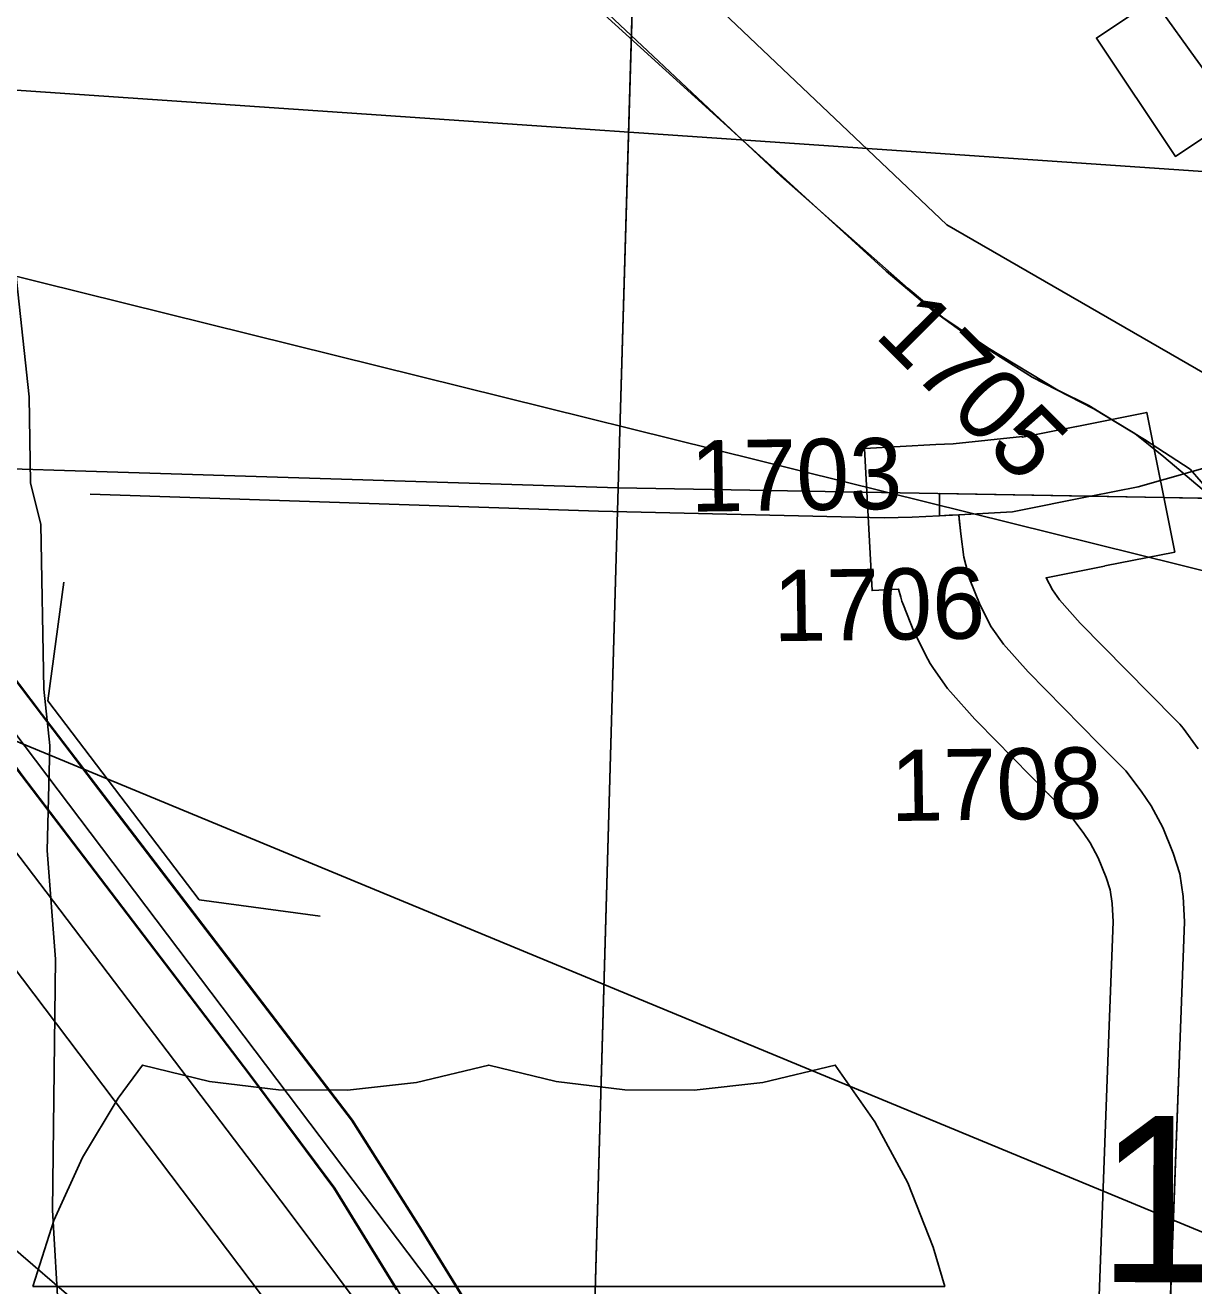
# Model space of a CAD drawing. Extents: x -132.8 to -73.3, y -60 to -26.
# Drawn here: x -121.236 to -120.744, y -52.636 to -52.105 of the extents above; entities that cross this region are included whole.
import ezdxf

# ---------------------------------------------------------------- set-up
doc = ezdxf.new("R2010")
doc.units = 0
for name, color, linetype in [('tdCoCityStreetMajor', 7, 'Continuous'), ('tdCoCityStreetMinor', 7, 'Continuous'), ('tdCoCorpBndry', 7, 'Continuous'), ('tdCoDivCarto', 7, 'Continuous'), ('tdCoHydroRiver', 7, 'Continuous'), ('tdCoInt', 7, 'Continuous'), ('tdCoIntCL', 7, 'Continuous'), ('tdCoIntRte', 7, 'Continuous'), ('tdCoPipe', 7, 'Continuous'), ('tdCoPrimary', 7, 'Continuous'), ('tdCoRRCL', 7, 'Continuous'), ('tdCoSecRdNmbr', 7, 'Continuous'), ('tdCoSecRteBand', 7, 'Continuous'), ('tdCoSecRteCL', 7, 'Continuous'), ('tdCoSectLine', 7, 'Continuous'), ('tdCoSectLinePart', 7, 'Continuous'), ('tdCoShieldInt', 7, 'Continuous'), ('tdCoStrucDivPri', 7, 'Continuous'), ('tdCoStrucPriMaintName', 7, 'Continuous'), ('tdCoSurfAsphalt', 7, 'Continuous'), ('tdCoSurfConc', 7, 'Continuous'), ('tdCoTwpBndryShd', 7, 'Continuous')]:
    doc.layers.add(name, color=color, linetype=linetype)

msp = doc.modelspace()

# ---------------------------------------------------------------- linework, layer by layer
at = {"layer": 'tdCoCityStreetMajor'}
msp.add_lwpolyline([(-120.60174, -52.30666), (-120.61699, -52.28936), (-120.62475, -52.27974), (-120.63252, -52.27012), (-120.65644, -52.23708), (-120.67864, -52.20674), (-120.70774, -52.16778), (-120.74333, -52.11864), (-120.75811, -52.09824), (-120.82426, -52.009), (-120.92699, -51.86988), (-120.95346, -51.83403), (-120.97689, -51.80321)], dxfattribs=at)
at = {"layer": 'tdCoCityStreetMinor'}
for points in [[(-120.78726, -52.30337), (-120.76731, -52.29938), (-120.73328, -52.28977), (-120.71799, -52.28656), (-120.69999, -52.28631), (-120.68124, -52.28829), (-120.66226, -52.29051), (-120.64795, -52.29026), (-120.63636, -52.28705), (-120.62475, -52.27974)], [(-121.2088, -52.3025), (-120.99468, -52.30974), (-120.97672, -52.31015), (-120.87434, -52.31245), (-120.8625, -52.31221), (-120.85106, -52.3116)]]:
    msp.add_lwpolyline(points, dxfattribs=at)
at = {"layer": 'tdCoCorpBndry'}
msp.add_lwpolyline([(-120.6017, -52.30669), (-120.78738, -52.3034), (-120.85097, -52.30227), (-120.85106, -52.3116), (-120.8469, -52.31139), (-120.84289, -52.31118), (-120.84269, -52.31311), (-120.84207, -52.31917), (-120.84084, -52.32903), (-120.83837, -52.33816), (-120.83393, -52.34925), (-120.82924, -52.35838), (-120.82407, -52.36578), (-120.81371, -52.37737), (-120.78387, -52.4077), (-120.77253, -52.41904), (-120.76611, -52.42767), (-120.76192, -52.43384), (-120.75699, -52.44296), (-120.75255, -52.45381), (-120.74984, -52.46245), (-120.74836, -52.47206), (-120.74786, -52.48267), (-120.74959, -52.52755), (-120.75699, -52.72878)], dxfattribs=at)
at = {"layer": 'tdCoDivCarto'}
for p, q in [((-121.22895, -52.3953), (-121.28412, -52.32282)), ((-121.22895, -52.3953), (-121.28412, -52.32282)), ((-121.20476, -52.42706), (-121.22895, -52.3953)), ((-121.23709, -52.42131), (-121.1416, -52.54679)), ((-121.09833, -52.56629), (-121.20476, -52.42706)), ((-121.1416, -52.54679), (-121.10569, -52.59493)), ((-121.06892, -52.61261), (-121.09833, -52.56629)), ((-121.10569, -52.59493), (-121.07931, -52.63776)), ((-121.0447, -52.65216), (-121.06892, -52.61261))]:
    msp.add_line(p, q, dxfattribs=at)
for points in [[(-121.22895, -52.3953), (-121.28412, -52.32282)], [(-121.22895, -52.3953), (-121.28412, -52.32282)], [(-121.30067, -52.33477), (-121.28052, -52.36157), (-121.23709, -52.42131), (-121.1416, -52.54679), (-121.10569, -52.59493), (-121.07931, -52.63776), (-121.06353, -52.66538), (-121.05077, -52.6997), (-121.04276, -52.72947), (-121.03525, -52.77967), (-121.03371, -52.80045)], [(-121.30067, -52.33477), (-121.28052, -52.36157), (-121.23709, -52.42131), (-121.1416, -52.54679), (-121.10569, -52.59493), (-121.07931, -52.63776), (-121.06353, -52.66538), (-121.05077, -52.6997), (-121.04276, -52.72947), (-121.03525, -52.77967), (-121.03371, -52.80045)], [(-121.30067, -52.33477), (-121.28052, -52.36157), (-121.23709, -52.42131), (-121.1416, -52.54679), (-121.10569, -52.59493), (-121.07931, -52.63776), (-121.06353, -52.66538), (-121.05077, -52.6997), (-121.04691, -52.71403)], [(-121.01318, -52.80059), (-121.01294, -52.79459), (-121.01535, -52.77005), (-121.01775, -52.74839), (-121.02401, -52.71086), (-121.03267, -52.68199), (-121.0447, -52.65216), (-121.06892, -52.61261), (-121.09833, -52.56629), (-121.20476, -52.42706), (-121.22895, -52.3953)], [(-121.01318, -52.80059), (-121.01294, -52.79459), (-121.01535, -52.77005), (-121.01775, -52.74839), (-121.02401, -52.71086), (-121.03267, -52.68199), (-121.0447, -52.65216), (-121.06892, -52.61261), (-121.09833, -52.56629), (-121.20476, -52.42706), (-121.22895, -52.3953)], [(-121.02993, -52.69113), (-121.03267, -52.68199), (-121.0447, -52.65216), (-121.06892, -52.61261), (-121.09833, -52.56629), (-121.20476, -52.42706), (-121.22895, -52.3953)]]:
    msp.add_lwpolyline(points, dxfattribs=at)
at = {"layer": 'tdCoHydroRiver'}
msp.add_lwpolyline([(-121.16983, -51.55955), (-121.24268, -51.74534), (-121.27519, -51.83913), (-121.27697, -51.90535), (-121.27121, -51.92602), (-121.27014, -51.94498), (-121.259, -52.0005), (-121.25815, -52.02735), (-121.24978, -52.06859), (-121.24918, -52.1049), (-121.24303, -52.16976), (-121.24076, -52.20295), (-121.23444, -52.2615), (-121.23383, -52.29781), (-121.22957, -52.31528), (-121.22828, -52.38474), (-121.22575, -52.40847), (-121.22694, -52.45262), (-121.22343, -52.49847), (-121.22469, -52.60415), (-121.21926, -52.6958)], dxfattribs=at)
at = {"layer": 'tdCoInt'}
for points in [[(-121.0437, -54.22753), (-121.01044, -53.28743), (-120.99348, -52.85325), (-120.99624, -52.80748), (-121.00242, -52.7704), (-121.01259, -52.73257), (-121.02781, -52.69535), (-121.04715, -52.65895), (-121.42997, -52.15232)], [(-121.10315, -54.21139), (-121.0704, -53.28521), (-121.05355, -52.85415), (-121.05595, -52.81423), (-121.06113, -52.78315), (-121.06955, -52.75179), (-121.08221, -52.72085), (-121.09798, -52.69116), (-121.47262, -52.19536)]]:
    msp.add_lwpolyline(points, dxfattribs=at)
at = {"layer": 'tdCoIntCL'}
msp.add_lwpolyline([(-121.04104, -53.29303), (-121.03435, -53.13559), (-121.03326, -53.10867), (-121.03251, -53.09119), (-121.03189, -53.07618), (-121.02716, -52.94878), (-121.02351, -52.85371), (-121.02358, -52.85261), (-121.02609, -52.81085), (-121.0279, -52.8), (-121.03177, -52.77677), (-121.04107, -52.74218), (-121.04636, -52.72925), (-121.05501, -52.7081), (-121.07257, -52.67505), (-121.12575, -52.6038), (-121.1985, -52.508), (-121.29295, -52.38365), (-121.31746, -52.35092)], dxfattribs=at)
at = {"layer": 'tdCoIntRte'}
for points in [[(-121.84525, -51.66339), (-121.79308, -51.73254), (-121.7793, -51.75081), (-121.75967, -51.77683), (-121.75945, -51.77705), (-121.69201, -51.84623), (-121.64363, -51.89696), (-121.63105, -51.91015), (-121.58015, -51.96578), (-121.54918, -51.99991), (-121.52807, -52.02655), (-121.48134, -52.08708), (-121.47066, -52.10092), (-121.45408, -52.12243), (-121.42331, -52.16248), (-121.37793, -52.22541), (-121.3675, -52.24033), (-121.34676, -52.27), (-121.27958, -52.36333), (-121.24437, -52.41224), (-121.14198, -52.54679), (-121.10607, -52.59493), (-121.07969, -52.63776)], [(-121.04508, -52.65216), (-121.0693, -52.61261), (-121.09871, -52.56629), (-121.16364, -52.48135), (-121.20514, -52.42706), (-121.22933, -52.3953), (-121.2845, -52.32282), (-121.28646, -52.32025), (-121.29333, -52.31122), (-121.33532, -52.25608), (-121.44246, -52.11534), (-121.47053, -52.07803), (-121.49694, -52.04293), (-121.5231, -52.00816), (-121.56955, -51.94793), (-121.57936, -51.93141), (-121.61367, -51.87366), (-121.65892, -51.7975), (-121.66529, -51.78677), (-121.66907, -51.77882), (-121.68529, -51.74469), (-121.70512, -51.70568), (-121.71488, -51.68649)], [(-121.04508, -52.65216), (-121.0693, -52.61261), (-121.09871, -52.56629), (-121.20514, -52.42706), (-121.22933, -52.3953), (-121.2845, -52.32282), (-121.28646, -52.32025), (-121.29333, -52.31122), (-121.33532, -52.25608), (-121.44246, -52.11534), (-121.47053, -52.07803), (-121.49694, -52.04293), (-121.5231, -52.00816), (-121.56887, -51.94789), (-121.57936, -51.93141), (-121.61607, -51.87508), (-121.61711, -51.87349), (-121.64907, -51.8151), (-121.65909, -51.7976), (-121.66529, -51.78677), (-121.66907, -51.77882), (-121.68529, -51.74469), (-121.70512, -51.70568), (-121.71488, -51.68649)], [(-121.23747, -52.42131), (-121.14198, -52.54679), (-121.10607, -52.59493), (-121.07969, -52.63776)]]:
    msp.add_lwpolyline(points, dxfattribs=at)
at = {"layer": 'tdCoPipe'}
msp.add_lwpolyline([(-119.79665, -53.49603), (-120.03098, -53.27088), (-120.31929, -53.03672), (-120.68529, -52.8785), (-121.0012, -52.82656), (-121.49047, -52.40565), (-121.39982, -51.55717), (-121.23691, -50.91275), (-120.91445, -50.41851), (-120.40095, -49.58835), (-120.25565, -49.23166), (-120.19476, -48.57334), (-120.22335, -47.97882), (-119.95841, -47.76157), (-119.94709, -47.38436)], dxfattribs=at)
at = {"layer": 'tdCoPrimary'}
msp.add_line((-121.22895, -52.3953), (-121.28412, -52.32282), dxfattribs=at)
msp.add_line((-121.22895, -52.3953), (-121.28412, -52.32282), dxfattribs=at)
for points in [[(-121.03281, -53.29329), (-121.03189, -53.26526), (-121.02696, -53.15133), (-121.02539, -53.10894), (-121.02228, -53.02482), (-121.01921, -52.94909), (-121.01382, -52.81629), (-121.01324, -52.80185), (-121.01294, -52.79459), (-121.01535, -52.77005), (-121.01775, -52.74839), (-121.02401, -52.71086), (-121.02993, -52.69113), (-121.03267, -52.68199), (-121.0447, -52.65216), (-121.06892, -52.61261), (-121.09833, -52.56629), (-121.20476, -52.42706), (-121.22895, -52.3953), (-121.28412, -52.32282)], [(-121.30067, -52.33477), (-121.28052, -52.36157), (-121.23709, -52.42131), (-121.1416, -52.54679), (-121.10569, -52.59493), (-121.07931, -52.63776), (-121.06353, -52.66538), (-121.05077, -52.6997), (-121.04691, -52.71403)], [(-121.30067, -52.33477), (-121.28052, -52.36157), (-121.23709, -52.42131), (-121.1416, -52.54679), (-121.10569, -52.59493), (-121.07931, -52.63776), (-121.06353, -52.66538), (-121.05077, -52.6997), (-121.04691, -52.71403)], [(-121.02993, -52.69113), (-121.03267, -52.68199), (-121.0447, -52.65216), (-121.06892, -52.61261), (-121.09833, -52.56629), (-121.20476, -52.42706), (-121.22895, -52.3953)], [(-121.02993, -52.69113), (-121.03267, -52.68199), (-121.0447, -52.65216), (-121.06892, -52.61261), (-121.09833, -52.56629), (-121.20476, -52.42706), (-121.22895, -52.3953)], [(-121.23709, -52.42131), (-121.1416, -52.54679), (-121.10569, -52.59493), (-121.07931, -52.63776), (-121.06353, -52.66538), (-121.05077, -52.6997), (-121.04691, -52.71403), (-121.04276, -52.72947), (-121.03525, -52.77967), (-121.03354, -52.80277), (-121.03255, -52.81603), (-121.03181, -52.83403), (-121.03157, -52.85919), (-121.03304, -52.91393), (-121.03699, -53.03206), (-121.0383, -53.0688), (-121.03882, -53.08333), (-121.04032, -53.12524), (-121.04192, -53.17016), (-121.04587, -53.23773), (-121.04907, -53.3339)]]:
    msp.add_lwpolyline(points, dxfattribs=at)
at = {"layer": 'tdCoRRCL'}
for points in [[(-120.72868, -52.31026), (-120.7566, -52.28681), (-120.76882, -52.27703), (-120.7776, -52.27159), (-120.78813, -52.26516), (-120.80116, -52.25866), (-120.83066, -52.24084), (-120.84959, -52.22804), (-120.86424, -52.21583), (-120.91792, -52.16852), (-120.99031, -52.10038), (-121.03912, -52.05793), (-121.03947, -52.05745), (-121.08997, -52.01165), (-121.1628, -51.9468), (-121.22019, -51.89183), (-121.25673, -51.85775), (-121.25709, -51.85774), (-121.31364, -51.79806), (-121.50653, -51.60846)], [(-120.73617, -52.30266), (-120.74548, -52.29203), (-120.76465, -52.27951), (-120.78596, -52.26659), (-120.81199, -52.25323), (-120.83599, -52.23811), (-120.85375, -52.2253), (-120.87348, -52.20854), (-120.92214, -52.16418), (-120.99833, -52.09497), (-121.01256, -52.08204), (-121.07569, -52.02454), (-121.19801, -51.91315), (-121.24733, -51.86452), (-121.24789, -51.86398), (-121.27791, -51.83495), (-121.28453, -51.82834), (-121.40845, -51.7045), (-121.47732, -51.63614)], [(-121.17763, -51.8759), (-120.84801, -52.18904), (-120.73915, -52.25184)]]:
    msp.add_lwpolyline(points, dxfattribs=at)
at = {"layer": 'tdCoSecRteBand'}
for points in [[(-120.72669, -52.1436), (-120.75165, -52.16024), (-120.78493, -52.11032), (-120.76208, -52.09508), (-120.7617, -52.06845), (-120.76169, -52.0681), (-120.76168, -52.06775), (-120.76107, -52.05161), (-120.75922, -52.00232), (-120.75728, -51.92855), (-120.75701, -51.91791), (-120.75699, -51.91743), (-120.75696, -51.91694), (-120.7523, -51.83711), (-120.75079, -51.79705), (-120.74738, -51.70668), (-120.74718, -51.69804)], [(-120.78697, -52.72768), (-120.77957, -52.52645), (-120.77957, -52.52642), (-120.77957, -52.5264), (-120.77789, -52.48279), (-120.77825, -52.47505), (-120.77914, -52.46926), (-120.78079, -52.46401), (-120.78415, -52.45581), (-120.78759, -52.44945), (-120.79057, -52.44506), (-120.79529, -52.4387), (-120.80508, -52.42891), (-120.80517, -52.42882), (-120.80526, -52.42874), (-120.83509, -52.3984), (-120.8356, -52.39789), (-120.83608, -52.39736), (-120.84644, -52.38576), (-120.84762, -52.38444), (-120.84864, -52.38298), (-120.85382, -52.37558), (-120.855, -52.3739), (-120.85593, -52.37208), (-120.86062, -52.36296), (-120.86126, -52.3617), (-120.86178, -52.36039), (-120.86622, -52.3493), (-120.86687, -52.34767), (-120.86733, -52.34598), (-120.86826, -52.34255), (-120.87944, -52.34314), (-120.88259, -52.28322), (-120.85263, -52.28165), (-120.84522, -52.28126), (-120.81613, -52.27826), (-120.8161, -52.27855), (-120.79326, -52.27398), (-120.79326, -52.27398), (-120.79325, -52.27398), (-120.79313, -52.27395), (-120.76371, -52.26808), (-120.75196, -52.32692), (-120.78138, -52.33279), (-120.7815, -52.33282), (-120.80612, -52.33774), (-120.80349, -52.34285), (-120.80051, -52.34711), (-120.79182, -52.35684), (-120.76257, -52.38657), (-120.75131, -52.39783), (-120.74976, -52.39939), (-120.74844, -52.40115), (-120.74203, -52.40978)]]:
    msp.add_lwpolyline(points, dxfattribs=at)
at = {"layer": 'tdCoSecRteCL'}
msp.add_line((-120.85106, -52.3116), (-120.84289, -52.31118), dxfattribs=at)
for points in [[(-120.84289, -52.31118), (-120.82033, -52.30999), (-120.78738, -52.3034), (-120.78726, -52.30337)], [(-120.75414, -52.65116), (-120.74959, -52.52755), (-120.74786, -52.48267), (-120.74836, -52.47206), (-120.74984, -52.46244), (-120.75255, -52.45381), (-120.75699, -52.44296), (-120.76192, -52.43384), (-120.76611, -52.42767), (-120.77253, -52.41904), (-120.78387, -52.4077), (-120.81371, -52.37737), (-120.82407, -52.36578), (-120.82924, -52.35838), (-120.83393, -52.34925), (-120.83837, -52.33816), (-120.84084, -52.32903), (-120.84207, -52.31917), (-120.84289, -52.31118)]]:
    msp.add_lwpolyline(points, dxfattribs=at)
at = {"layer": 'tdCoSectLine'}
for points in [[(-120.98644, -52.29987), (-120.95707, -51.30108)], [(-121.95502, -52.2695), (-120.98644, -52.29987)], [(-121.01456, -53.29268), (-121.01115, -53.1722), (-121.00063, -52.80087), (-120.98644, -52.29987)], [(-120.98644, -52.29987), (-119.98023, -52.31774)]]:
    msp.add_lwpolyline(points, dxfattribs=at)
at = {"layer": 'tdCoSectLinePart'}
msp.add_lwpolyline([(-120.75, -52.30407), (-120.64268, -52.30597)], dxfattribs=at)
at = {"layer": 'tdCoShieldInt'}
msp.add_lwpolyline([(-121.23288, -52.63632), (-121.22404, -52.60853), (-121.21202, -52.58196), (-121.19699, -52.55697), (-121.18679, -52.5431), (-121.15845, -52.54998), (-121.1295, -52.55351), (-121.10033, -52.55364), (-121.07135, -52.55036), (-121.04086, -52.5431), (-121.01252, -52.54998), (-120.98357, -52.55351), (-120.9544, -52.55364), (-120.92543, -52.55036), (-120.89493, -52.5431), (-120.87821, -52.567), (-120.86439, -52.59268), (-120.85366, -52.61979), (-120.84883, -52.63632)], dxfattribs=at)
msp.add_lwpolyline([(-121.23288, -52.63632), (-121.22404, -52.60853), (-121.21202, -52.58196), (-121.19699, -52.55697), (-121.18679, -52.5431), (-121.15845, -52.54998), (-121.1295, -52.55351), (-121.10033, -52.55364), (-121.07135, -52.55036), (-121.04086, -52.5431), (-121.01252, -52.54998), (-120.98357, -52.55351), (-120.9544, -52.55364), (-120.92543, -52.55036), (-120.89493, -52.5431), (-120.87821, -52.567), (-120.86439, -52.59268), (-120.85366, -52.61979), (-120.84883, -52.63632)], close=True, dxfattribs=at)
at = {"layer": 'tdCoStrucDivPri'}
for p, q in [((-121.22663, -52.38956), (-121.2198, -52.33961)), ((-121.22663, -52.38956), (-121.16292, -52.47345)), ((-121.16292, -52.47345), (-121.11195, -52.4804))]:
    msp.add_line(p, q, dxfattribs=at)
at = {"layer": 'tdCoStrucPriMaintName'}
for p, q in [((-120.67367, -52.17112), (-121.50222, -52.11427)), ((-120.67367, -52.17112), (-121.50222, -52.11427)), ((-120.67367, -52.17112), (-121.50222, -52.11427)), ((-120.7077, -52.34275), (-121.45938, -52.15628)), ((-120.7077, -52.34275), (-121.45938, -52.15628)), ((-120.7077, -52.34275), (-121.45938, -52.15628)), ((-120.7077, -52.627), (-121.43528, -52.32572)), ((-120.7077, -52.627), (-121.43528, -52.32572)), ((-120.7077, -52.627), (-121.43528, -52.32572))]:
    msp.add_line(p, q, dxfattribs=at)
at = {"layer": 'tdCoSurfAsphalt'}
msp.add_lwpolyline([(-120.76048, -52.82504), (-120.7598, -52.80815), (-120.75847, -52.77539), (-120.75699, -52.72878), (-120.74959, -52.52755), (-120.74786, -52.48267), (-120.74836, -52.47206), (-120.74984, -52.46244), (-120.75255, -52.45381), (-120.75699, -52.44296), (-120.76192, -52.43384), (-120.76611, -52.42767), (-120.77253, -52.41904), (-120.78387, -52.4077), (-120.81371, -52.37737), (-120.82407, -52.36578), (-120.82924, -52.35838), (-120.83393, -52.34925), (-120.83837, -52.33816), (-120.84084, -52.32903), (-120.84207, -52.31917), (-120.84289, -52.31118)], dxfattribs=at)
at = {"layer": 'tdCoSurfConc'}
msp.add_lwpolyline([(-120.85106, -52.3116), (-120.84289, -52.31118), (-120.82033, -52.30999), (-120.78738, -52.3034), (-120.78726, -52.30337)], dxfattribs=at)
at = {"layer": 'tdCoTwpBndryShd'}
msp.add_lwpolyline([(-122.06359, -55.27827), (-122.03223, -55.27864), (-121.07675, -55.30969), (-121.05003, -54.29547), (-121.01456, -53.29268), (-121.01115, -53.1722), (-121.00063, -52.80087), (-120.98644, -52.29987), (-120.95707, -51.30108), (-120.93809, -50.82388), (-120.91911, -50.34667), (-120.89993, -49.84653), (-120.88076, -49.34639), (-120.88334, -48.34969), (-120.84389, -47.35854), (-120.84385, -47.34845), (-120.82083, -46.35535), (-120.79273, -45.36236), (-120.75071, -44.39009)], dxfattribs=at)

# ---------------------------------------------------------------- texts
at = {"layer": 'tdCoSecRdNmbr'}
for s, height, rotation, p in [('1705', 0.03, 314.9099, (-120.87885, -52.23585)), ('1703', 0.03, 0.7622, (-120.95581, -52.30992)), ('1706', 0.03, 0.7622, (-120.9209, -52.36451)), ('1708', 0.03, 0.7622, (-120.87154, -52.44028)), ('1710', 0.07, 359.91, (-120.78451, -52.63452))]:
    msp.add_text(s, height=height, rotation=rotation, dxfattribs=at).set_placement(p)

doc.saveas('drawing.dxf')
